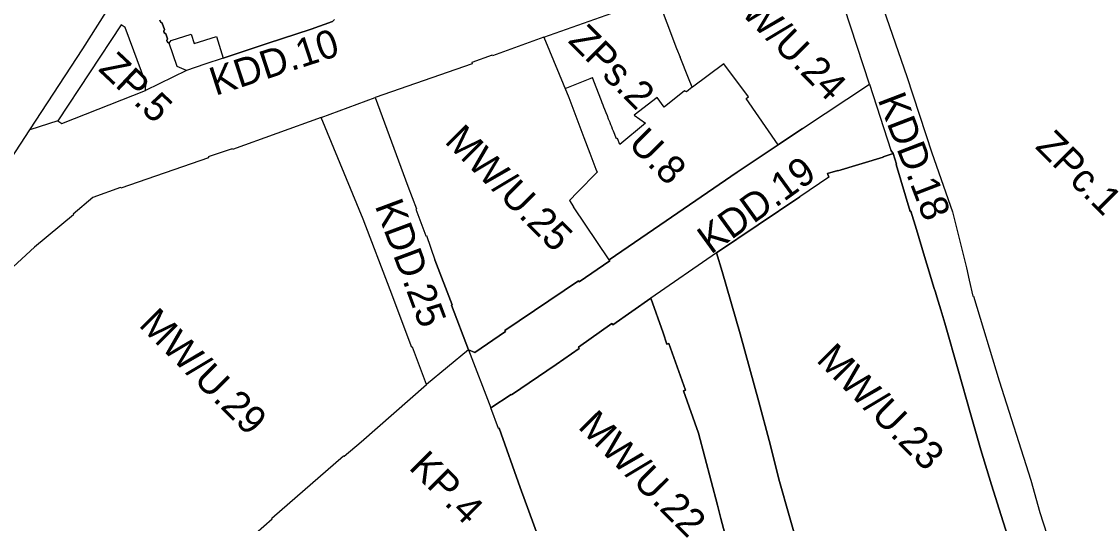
# Model space of a CAD drawing. Extents: x 7423835 to 7425280, y 5546086 to 5547600.
# Drawn here: x 7424365.2 to 7424593.5, y 5546727.5 to 5546834 of the extents above; entities that cross this region are included whole.
import ezdxf

# ---------------------------------------------------------------- set-up
doc = ezdxf.new("R2010")
doc.units = 0
for name, color, linetype in [('linie rozgraniczające', 7, 'Continuous'), ('obowiazujace linie zabudowy', 7, 'Continuous'), ('przeznaczenia terenów', 7, 'Continuous')]:
    doc.layers.add(name, color=color, linetype=linetype)

msp = doc.modelspace()

# ---------------------------------------------------------------- linework, layer by layer
at = {"layer": 'linie rozgraniczające'}
for p, q in [((7424506.73, 5546821.97), (7424504.92, 5546826.44)), ((7424400.18, 5546823.64), (7424391.46, 5546819.4)), ((7424545.11, 5546820.7), (7424549.68, 5546806.67)), ((7424428.76, 5546813.61), (7424440.21, 5546817.87)), ((7424372.86, 5546812.93), (7424366.91, 5546810.99)), ((7424536.47, 5546800.97), (7424530.31, 5546796.82)), ((7424489.87, 5546783.42), (7424482.31, 5546794.71)), ((7424512.66, 5546784.92), (7424498.75, 5546775.3)), ((7424460.01, 5546764.32), (7424451.13, 5546756.99)), ((7424460.01, 5546764.32), (7424464.75, 5546751.99)), ((7424466.37, 5546747.65), (7424464.75, 5546751.99))]:
    msp.add_line(p, q, dxfattribs=at)
for points in [[(7424530.89, 5546811.29), (7424545.11, 5546820.7), (7424538.49, 5546841.09), (7424536.21, 5546848.35), (7424535.46, 5546850.59), (7424533.77, 5546851.51), (7424530.46, 5546850.39), (7424522.88, 5546847.46), (7424500.08, 5546839.22)], [(7424291.6, 5546795.75), (7424291.81, 5546792.57), (7424297.85, 5546785.83), (7424298.01, 5546785.97), (7424301.66, 5546782.01), (7424301.72, 5546782.05), (7424319.01, 5546763.01), (7424331.35, 5546773.85), (7424340.6, 5546782.3), (7424349.73, 5546790.56), (7424358.93, 5546798.87), (7424366.91, 5546810.99), (7424378.18, 5546828.24), (7424386.41, 5546841.23)], [(7424476.01, 5546830.71), (7424500.08, 5546839.22), (7424504.17, 5546828.3), (7424504.92, 5546826.44)], [(7424546.87, 5546840.16), (7424553.07, 5546822.35), (7424558.38, 5546806.12), (7424562.73, 5546793.62), (7424565.74, 5546781.7), (7424566.26, 5546779.13), (7424567.08, 5546775.74), (7424567.21, 5546775.74), (7424572.61, 5546757.78), (7424579.36, 5546736.66), (7424581.27, 5546729.79), (7424582.77, 5546725.18), (7424583.4, 5546722.97), (7424583.5, 5546722.97), (7424583.6, 5546722.64)], [(7424431.16, 5546834.04), (7424426.61, 5546832.41), (7424417.29, 5546829.33), (7424407.98, 5546826.26), (7424404.08, 5546824.95), (7424400.18, 5546823.64), (7424398.2, 5546824.44), (7424396.52, 5546829.44), (7424396.18, 5546829.62), (7424396.05, 5546829.99), (7424396.13, 5546830.33), (7424395.83, 5546831.4), (7424395.48, 5546831.58), (7424395.36, 5546831.93), (7424395.53, 5546832.29), (7424395.01, 5546833.65), (7424394.66, 5546833.91), (7424394.53, 5546834.28)], [(7424476.01, 5546830.71), (7424465.12, 5546826.7), (7424465.06, 5546826.86), (7424460.77, 5546825.28), (7424460.8, 5546825.06), (7424440.21, 5546817.87), (7424447.18, 5546799.09), (7424449, 5546794.22), (7424448.85, 5546794.16), (7424450.95, 5546788.51), (7424451.1, 5546788.56), (7424452.92, 5546783.45)], [(7424476.01, 5546830.71), (7424481.3, 5546817.91), (7424484.52, 5546809.38), (7424485.78, 5546806.07), (7424487.07, 5546802.67), (7424487.33, 5546802.06), (7424483.18, 5546797.77), (7424481.45, 5546795.99), (7424482.31, 5546794.71)], [(7424525.76, 5546807.81), (7424518.96, 5546817.68), (7424519.44, 5546818.03), (7424514.24, 5546825.06), (7424507.55, 5546820.09), (7424507.5, 5546820.05), (7424506.73, 5546821.97)], [(7424480.54, 5546819.76), (7424485.84, 5546821.94), (7424486.34, 5546822.14)], [(7424490.1, 5546812.47), (7424490.07, 5546812.55), (7424489.88, 5546813.02), (7424489.77, 5546813.31), (7424489.5, 5546813.99), (7424489.23, 5546814.66), (7424488.96, 5546815.34), (7424488.77, 5546815.8), (7424488.59, 5546816.27), (7424488.4, 5546816.73), (7424488.22, 5546817.2), (7424486.66, 5546821.35), (7424486.34, 5546822.14)], [(7424507.5, 5546820.05), (7424506.3, 5546819.07), (7424505.84, 5546819.29), (7424501.55, 5546815.82), (7424500.08, 5546817.85), (7424495.17, 5546814.1), (7424497.58, 5546812.42), (7424492.17, 5546807.94), (7424491.67, 5546809.16), (7424491.61, 5546809.22), (7424491.42, 5546809.14), (7424490.79, 5546810.72), (7424490.62, 5546811.16), (7424490.44, 5546811.62), (7424490.25, 5546812.09), (7424490.1, 5546812.47)], [(7424451.13, 5546756.99), (7424448.14, 5546764.88), (7424448.03, 5546764.84), (7424443.44, 5546777.08), (7424437.68, 5546792.08), (7424428.76, 5546813.61), (7424409.93, 5546806.81), (7424409.85, 5546806.98), (7424404.81, 5546805.28), (7424404.87, 5546805.11), (7424386.23, 5546798.64), (7424386.18, 5546798.78), (7424380.33, 5546796.63), (7424376.13, 5546793.13), (7424376.22, 5546793.01), (7424367.92, 5546786.13), (7424355.21, 5546774.47)], [(7424530.89, 5546811.29), (7424525.76, 5546807.81), (7424517.03, 5546802), (7424500.63, 5546790.76), (7424489.87, 5546783.42), (7424490.03, 5546783.19), (7424483.52, 5546778.75), (7424483.38, 5546778.96), (7424467.75, 5546768.44), (7424467.9, 5546768.23), (7424461.36, 5546763.76), (7424460.01, 5546764.32), (7424456.39, 5546773.82), (7424456.55, 5546773.89), (7424452.92, 5546783.45)], [(7424549.68, 5546806.67), (7424550.18, 5546806.02), (7424550.86, 5546803.72), (7424550.75, 5546803.67), (7424553.78, 5546793.71), (7424553.9, 5546793.74), (7424555.07, 5546789.88), (7424556.24, 5546786.02), (7424556.8, 5546784.13), (7424557.79, 5546780.85), (7424558.79, 5546777.57), (7424559.11, 5546776.59), (7424559.43, 5546775.61), (7424560.29, 5546772.82), (7424561.14, 5546770.02), (7424564.03, 5546759.83), (7424566.48, 5546751.02), (7424568.78, 5546743.12), (7424571.01, 5546735.66), (7424573.5, 5546727.81), (7424575.32, 5546722.07)], [(7424536.47, 5546800.97), (7424536.22, 5546801.75), (7424538.42, 5546802.42), (7424538.44, 5546802.34), (7424548.05, 5546805.21), (7424548.02, 5546805.32), (7424550.18, 5546806.02)], [(7424533.19, 5546710.4), (7424530.14, 5546721.98), (7424526.01, 5546736.37), (7424523.85, 5546745.11), (7424521.65, 5546753.29), (7424517.7, 5546767.71), (7424513.85, 5546780.93), (7424512.66, 5546784.92), (7424530.31, 5546796.82)], [(7424464.75, 5546751.99), (7424469.07, 5546754.87), (7424469.16, 5546754.75), (7424478.62, 5546761.19), (7424483.55, 5546764.6), (7424483.34, 5546764.91), (7424490.45, 5546769.94), (7424490.67, 5546769.63), (7424498.75, 5546775.3), (7424501.31, 5546767.91), (7424502.15, 5546765.5), (7424502.53, 5546765.64), (7424506.05, 5546755.74), (7424505.67, 5546755.61), (7424508.84, 5546746.65), (7424512.85, 5546731.38), (7424513.61, 5546728.52), (7424518.32, 5546710.75)], [(7424411.49, 5546686.07), (7424406.27, 5546699.92), (7424401.12, 5546713.85), (7424401.96, 5546714.58), (7424414.65, 5546725.53), (7424414.8, 5546725.36), (7424418.35, 5546728.48), (7424418.27, 5546728.6), (7424433.52, 5546741.82), (7424433.64, 5546741.73), (7424437.27, 5546744.83), (7424451.13, 5546756.99)], [(7424475.76, 5546722.19), (7424471.03, 5546735.11), (7424466.51, 5546747.7), (7424466.37, 5546747.65)]]:
    msp.add_lwpolyline(points, dxfattribs=at)
msp.add_lwpolyline([(7424386.32, 5546833.31), (7424372.86, 5546812.93), (7424373.71, 5546812.33), (7424391.46, 5546819.4), (7424391.56, 5546820.91), (7424387.14, 5546832.74)], close=True, dxfattribs=at)
at = {"layer": 'obowiazujace linie zabudowy'}
for p, q in [((7424536.47, 5546800.97), (7424530.31, 5546796.82)), ((7424466.37, 5546747.65), (7424464.75, 5546751.99))]:
    msp.add_line(p, q, dxfattribs=at)
for points in [[(7424530.89, 5546811.29), (7424545.11, 5546820.7), (7424538.49, 5546841.09), (7424536.21, 5546848.35), (7424535.46, 5546850.59), (7424533.77, 5546851.51), (7424530.46, 5546850.39), (7424522.88, 5546847.46), (7424500.08, 5546839.22)], [(7424291.6, 5546795.75), (7424291.81, 5546792.57), (7424297.85, 5546785.83), (7424298.01, 5546785.97), (7424301.66, 5546782.01), (7424301.72, 5546782.05), (7424319.01, 5546763.01), (7424331.35, 5546773.85), (7424340.6, 5546782.3), (7424349.73, 5546790.56), (7424358.93, 5546798.87), (7424366.91, 5546810.99), (7424378.18, 5546828.24), (7424386.41, 5546841.23)], [(7424394.53, 5546834.28), (7424394.66, 5546833.91), (7424395.01, 5546833.65), (7424395.53, 5546832.29), (7424395.36, 5546831.93), (7424395.48, 5546831.58), (7424395.83, 5546831.4), (7424396.13, 5546830.33), (7424396.05, 5546829.99), (7424396.18, 5546829.62), (7424396.52, 5546829.44), (7424396.52, 5546829.44)], [(7424407.98, 5546826.26), (7424417.29, 5546829.33), (7424426.61, 5546832.41), (7424431.16, 5546834.04), (7424431.58, 5546834.43)], [(7424396.52, 5546829.44), (7424396.91, 5546829.97), (7424401.17, 5546831.33), (7424401.81, 5546829.33), (7424406.54, 5546830.86), (7424407.98, 5546826.26)], [(7424476.01, 5546830.71), (7424465.12, 5546826.7), (7424465.06, 5546826.86), (7424460.77, 5546825.28), (7424460.8, 5546825.06), (7424440.21, 5546817.87), (7424447.18, 5546799.09), (7424449, 5546794.22), (7424448.85, 5546794.16), (7424450.95, 5546788.51), (7424451.1, 5546788.56), (7424452.92, 5546783.45)], [(7424451.13, 5546756.99), (7424448.14, 5546764.88), (7424448.03, 5546764.84), (7424443.44, 5546777.08), (7424437.68, 5546792.08), (7424428.76, 5546813.61), (7424409.93, 5546806.81), (7424409.85, 5546806.98), (7424404.81, 5546805.28), (7424404.87, 5546805.11), (7424386.23, 5546798.64), (7424386.18, 5546798.78), (7424380.33, 5546796.63), (7424376.13, 5546793.13), (7424376.22, 5546793.01), (7424367.92, 5546786.13), (7424355.21, 5546774.47)], [(7424452.92, 5546783.45), (7424456.55, 5546773.89), (7424456.39, 5546773.82), (7424460.01, 5546764.32), (7424461.36, 5546763.76), (7424467.9, 5546768.23), (7424467.75, 5546768.44), (7424483.38, 5546778.96), (7424483.52, 5546778.75), (7424490.03, 5546783.19), (7424489.87, 5546783.42), (7424500.63, 5546790.76), (7424517.03, 5546802), (7424525.76, 5546807.81), (7424530.89, 5546811.29)], [(7424575.32, 5546722.07), (7424573.5, 5546727.81), (7424571.01, 5546735.66), (7424568.78, 5546743.12), (7424566.48, 5546751.02), (7424564.03, 5546759.83), (7424561.14, 5546770.02), (7424560.29, 5546772.82), (7424559.43, 5546775.61), (7424559.11, 5546776.59), (7424558.79, 5546777.57), (7424557.79, 5546780.85), (7424556.8, 5546784.13), (7424556.24, 5546786.02), (7424555.07, 5546789.88), (7424553.9, 5546793.74), (7424553.78, 5546793.71), (7424550.75, 5546803.67), (7424550.86, 5546803.72), (7424550.18, 5546806.02), (7424549.68, 5546806.67)], [(7424550.18, 5546806.02), (7424548.02, 5546805.32), (7424548.05, 5546805.21), (7424538.44, 5546802.34), (7424538.42, 5546802.42), (7424536.22, 5546801.75), (7424536.47, 5546800.97)], [(7424530.31, 5546796.82), (7424512.66, 5546784.92), (7424513.85, 5546780.93), (7424517.7, 5546767.71), (7424521.65, 5546753.29), (7424523.85, 5546745.11), (7424526.01, 5546736.37), (7424530.14, 5546721.98), (7424533.19, 5546710.4)], [(7424518.32, 5546710.75), (7424513.61, 5546728.52), (7424512.85, 5546731.38), (7424508.84, 5546746.65), (7424505.67, 5546755.61), (7424506.05, 5546755.74), (7424502.53, 5546765.64), (7424502.15, 5546765.5), (7424501.31, 5546767.91), (7424498.75, 5546775.3), (7424490.67, 5546769.63), (7424490.45, 5546769.94), (7424483.34, 5546764.91), (7424483.55, 5546764.6), (7424478.62, 5546761.19), (7424469.16, 5546754.75), (7424469.07, 5546754.87), (7424464.75, 5546751.99)], [(7424411.49, 5546686.07), (7424406.27, 5546699.92), (7424401.12, 5546713.85), (7424401.96, 5546714.58), (7424414.65, 5546725.53), (7424414.8, 5546725.36), (7424418.35, 5546728.48), (7424418.27, 5546728.6), (7424433.52, 5546741.82), (7424433.64, 5546741.73), (7424437.27, 5546744.83), (7424451.13, 5546756.99)], [(7424466.37, 5546747.65), (7424466.51, 5546747.7), (7424471.03, 5546735.11), (7424475.76, 5546722.19), (7424480.95, 5546708.39), (7424484.85, 5546697.87), (7424488.92, 5546687.19), (7424490.62, 5546682.75)]]:
    msp.add_lwpolyline(points, dxfattribs=at)

# ---------------------------------------------------------------- texts
at = {"layer": 'przeznaczenia terenów'}
for s, rotation, p in [('MW/U.24', 314.9764, (7424512.9, 5546840.43)), ('KDD.10', 18.0723, (7424406.32, 5546818.21)), ('ZPs.2', 314.9764, (7424480.96, 5546829.72)), ('ZP.5', 316.7216, (7424381.28, 5546823.72)), ('KDD.18', 290.9869, (7424546.81, 5546817.49)), ('MW/U.25', 314.9764, (7424454.76, 5546808.43)), ('U.8', 314.9764, (7424493.69, 5546807.77)), ('ZPc.1', 314.9764, (7424580.11, 5546807.25)), ('KDD.19', 35.8697, (7424511.45, 5546784.46)), ('KDD.25', 290.3933, (7424440.1, 5546794.93)), ('MW/U.29', 314.9764, (7424389.86, 5546769.48)), ('MW/U.23', 314.9764, (7424533.6, 5546762)), ('MW/U.22', 314.9764, (7424483.05, 5546747.82)), ('KP.4', 314.9764, (7424447.15, 5546739.21))]:
    msp.add_text(s, height=6, rotation=rotation, dxfattribs=at).set_placement(p)

doc.saveas('drawing.dxf')
